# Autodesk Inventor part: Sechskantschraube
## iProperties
Category: Inventor iPart's
Company: software factory
Shininess: 64.0
Length Units: 11269
Angle Units: 11279
Time Units: 11290
Mass Units: 11283
Length Display Precision: 3
Angle Display Precision: 3
Compacted: True
Part Number: Sechskantschraube
Document SubType Name: Modeling
Created: 2004-03
Material: 10.9
Designer: M.Grouls
Manufacturer: Standard
Standards Organization: Custom
Description: DIN 931 - M6x35 - 10.9
Project: Inventor iPart's
Density: 1 g/cm^3
Density: 0.0
Volumn: 0.0
Area: 0.0
PropertySet Name: Model Information
Control State: 0
Master: False
Checked Out: False
EINHEIT: Stck.
Author: M.Grouls
Title: Sechskantschraube
Subject: Inventor iPart's
Keywords: Normteil
Comments: Festigkeitsklassen: 8.8, 10.9, 12.9 Gewindegrößen bis M16x140
Revision Number: 12.1
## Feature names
1. Schraubenschaft [Extrusion]
2. Schraubenkopf [Extrusion]
3. 30Grad Schräge [Revolution]
4. Bund [Extrusion]
5. Fase [Chamfer]
